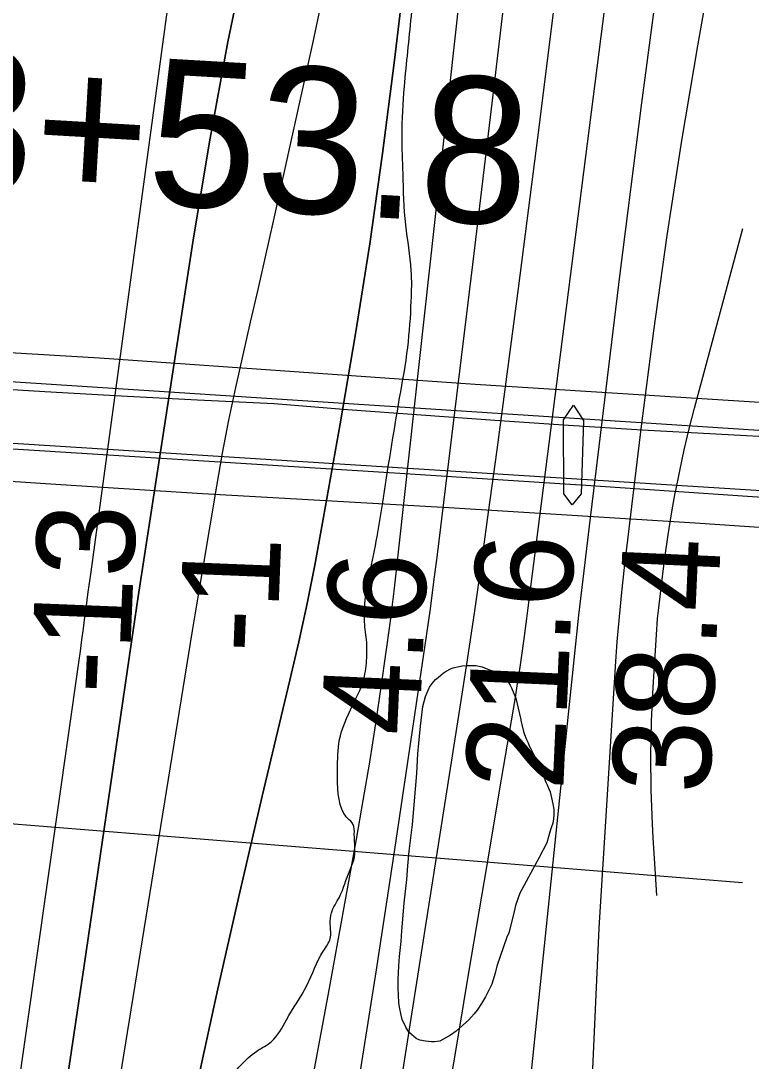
# Model space of a CAD drawing. Extents: x 3297716 to 3335574, y 688621 to 713991.
# Drawn here: x 3325046 to 3325545, y 704839 to 705550 of the extents above; entities that cross this region are included whole.
import ezdxf

# ---------------------------------------------------------------- set-up
doc = ezdxf.new("R2010")
doc.units = 0
for name, color, linetype in [('V-BRDG-OTLN', 7, 'Continuous'), ('V-CHAN-DOCK', 7, 'Continuous'), ('V-RIVR-EDGE', 7, 'Continuous'), ('V-RIVR-RANG', 7, 'Continuous'), ('V-ROAD-CNTR', 7, 'Continuous'), ('V-SITE-VEGE', 7, 'Continuous'), ('V-SURV-IDEN', 7, 'Continuous'), ('V-TOPO-DPTH', 7, 'Continuous'), ('V-TOPO-MAJR', 7, 'Continuous'), ('V-TOPO-MINR', 7, 'Continuous'), ('V-TOPO-WATR', 7, 'Continuous'), ('V-UTIL-LINE', 7, 'Continuous')]:
    doc.layers.add(name, color=color, linetype=linetype)

msp = doc.modelspace()

# ---------------------------------------------------------------- linework, layer by layer
at = {"layer": 'V-BRDG-OTLN'}
for points in [[(3324529.84, 705267.65), (3324534.06, 705355.13), (3324591.79, 705351.33), (3324800.22, 705337.75), (3325099.29, 705319.97), (3325356.02, 705301.98), (3325590.25, 705287.21), (3325902.56, 705266.18)], [(3324573.42, 705329.04), (3324643.35, 705324.88), (3324713.29, 705320.58), (3324783.21, 705316.14), (3324853.14, 705311.57), (3324905.3, 705307.55), (3324957.48, 705303.79), (3325009.68, 705300.29), (3325061.9, 705297.04), (3325114.13, 705294.05), (3325166.38, 705291.31), (3325218.65, 705288.83), (3325268.93, 705284.82), (3325319.23, 705281.02), (3325369.55, 705277.45), (3325419.88, 705274.1), (3325470.22, 705270.97), (3325520.58, 705268.06), (3325570.94, 705265.37), (3325659.01, 705260.29), (3325747.07, 705254.98), (3325835.11, 705249.45), (3325923.14, 705243.69)], [(3324593.65, 705285.89), (3324683.62, 705279.88), (3324773.62, 705274.04), (3324863.63, 705268.39), (3324953.65, 705262.91), (3325043.69, 705257.61), (3325174.19, 705249.55), (3325304.68, 705241.26), (3325435.16, 705232.75), (3325565.62, 705224.02), (3325696.06, 705215.08), (3325790.62, 705209.58), (3325885.17, 705203.87)], [(3325894.43, 705182.98), (3325821.2, 705187.47), (3325747.95, 705191.69), (3325674.68, 705195.66), (3325590.58, 705201.44), (3325506.46, 705207), (3325422.33, 705212.34), (3325338.18, 705217.46), (3325254.01, 705222.35), (3325169.83, 705227.03), (3325072.84, 705233.23), (3324975.84, 705239.55), (3324878.84, 705245.98), (3324781.83, 705252.51), (3324684.83, 705259.16), (3324609.48, 705263.15), (3324534.15, 705267.4), (3324529.84, 705267.65)]]:
    msp.add_lwpolyline(points, dxfattribs=at)
at = {"layer": 'V-CHAN-DOCK'}
msp.add_lwpolyline([(3325416.81, 705227), (3325416.57, 705277.78), (3325423.33, 705287.72), (3325430.2, 705277.22), (3325428.57, 705227.05), (3325422.42, 705219.59)], close=True, dxfattribs=at)
at = {"layer": 'V-RIVR-EDGE'}
msp.add_spline([(3324700.3, 701692.21), (3324707.78, 701736.4), (3324708.99, 701756.57), (3324710.58, 701771.69), (3324714.89, 701788.35), (3324722.34, 701822.07), (3324727.05, 701846.49), (3324726.7, 701860.46), (3324727.5, 701871.7), (3324731.02, 701883.32), (3324734.93, 701894.95), (3324738.07, 701910.07), (3324740.85, 701935.65), (3324742.08, 701963.57), (3324744.08, 701986.84), (3324750.35, 702014.74), (3324758.19, 702047.69), (3324765.99, 702067.83), (3324770.69, 702085.66), (3324776.59, 702119.38), (3324779, 702151.95), (3324775.93, 702165.53), (3324775.95, 702172.13), (3324776.75, 702182.21), (3324782.22, 702198.09), (3324784.57, 702207.4), (3324787.31, 702220.57), (3324790.84, 702234.91), (3324790.48, 702247.32), (3324788.58, 702261.68), (3324792.88, 702276.4), (3324795.23, 702286.48), (3324796.04, 702301.6), (3324796.1, 702322.16), (3324796.58, 702361.71), (3324797.04, 702388.47), (3324797.08, 702405.53), (3324798.28, 702420.65), (3324800.24, 702428.79), (3324800.25, 702434.22), (3324799.12, 702447.41), (3324799.13, 702452.84), (3324801.49, 702463.69), (3324801.9, 702472.61), (3324804.67, 702494.71), (3324803.17, 702516.82), (3324800.1, 702530.78), (3324799.37, 702550.18), (3324800.98, 702572.28), (3324801.8, 702588.95), (3324801.84, 702605.24), (3324799.92, 702613.39), (3324799.56, 702626.19), (3324799.61, 702646.74), (3324796.53, 702655.67), (3324796.55, 702664.2), (3324795.87, 702699.88), (3324799.07, 702741.75), (3324804.98, 702779.74), (3324812.05, 702815.01), (3324811.68, 702822.77), (3324810.22, 702858.07), (3324812.61, 702884.04), (3324819.67, 702918.15), (3324824.8, 702951.1), (3324831.5, 702996.46), (3324832.33, 703018.17), (3324835.5, 703046.86), (3324839.48, 703086.41), (3324850.1, 703144.94), (3324857.56, 703182.54), (3324864.24, 703218.2), (3324872.54, 703282.56), (3324900.83, 703429.08), (3324908.27, 703460.86), (3324916.46, 703480.61), (3324923.86, 703491.84), (3324931.26, 703505.01), (3324939.47, 703529.42), (3324949.64, 703567.01), (3324957.5, 703607.71), (3324964.97, 703649.19), (3324975.98, 703709.27), (3324982.57, 703710.03), (3324987.24, 703714.67), (3324987.29, 703735.23), (3324987.72, 703753.45), (3324992.41, 703770.12), (3324995.53, 703775.92), (3325004.46, 703777.84), (3325009.5, 703779.38), (3325011.06, 703783.64), (3325012.63, 703791.78), (3325016.97, 703820.47), (3325016.6, 703829), (3325013.93, 703846.07), (3325008.93, 703864.31), (3325004.69, 703873.24), (3325006.26, 703880.61), (3325008.99, 703887.58), (3325017.91, 703888.72), (3325028.38, 703888.31), (3325034.21, 703891.78), (3325035, 703896.82), (3325038.14, 703911.16), (3325044.39, 703929.37), (3325050.24, 703944.48), (3325054.93, 703959.21), (3325054.96, 703971.23), (3325056.93, 703984.8), (3325059.31, 704004.96), (3325061.26, 704009.61), (3325066.7, 704013.08), (3325069.03, 704017.34), (3325072.96, 704034.4), (3325083.15, 704079.75), (3325083.58, 704096.81), (3325081.31, 704118.53), (3325074.39, 704143.37), (3325068.22, 704159.67), (3325067.85, 704164.71), (3325072.94, 704185.64), (3325083.49, 704218.97), (3325091.32, 704246.87), (3325097.94, 704259.26), (3325105.32, 704263.9), (3325113.47, 704263.88), (3325125.09, 704261.52), (3325136.71, 704254.12), (3325147.54, 704241.3), (3325156.81, 704227.7), (3325159.92, 704228.86), (3325160.32, 704235.45), (3325158.78, 704241.66), (3325154.93, 704249.43), (3325146.03, 704261.08), (3325125.54, 704282.85), (3325115.1, 704298.78), (3325109.32, 704312.75), (3325105.86, 704323.62), (3325105.49, 704333.31), (3325105.52, 704342.23), (3325105.54, 704350.38), (3325117.67, 704396.5), (3325125.12, 704427.5), (3325138.44, 704482.15), (3325165.86, 704592.22), (3325178.75, 704632.52), (3325185.01, 704655.38), (3325194.42, 704694.53), (3325194.86, 704714.3), (3325191.4, 704727.5), (3325190.64, 704734.48), (3325194.56, 704751.14), (3325194.6, 704767.82), (3325194.64, 704786.05), (3325194.29, 704801.17), (3325187.35, 704813.99), (3325187.75, 704820.97), (3325189.32, 704827.56), (3325195.54, 704836.07), (3325206.82, 704846.13), (3325216.91, 704852.69), (3325227.03, 704867.41), (3325241.05, 704891.03), (3325252.36, 704914.65), (3325257.03, 704923.18), (3325257.06, 704932.87), (3325257.85, 704940.62), (3325263.31, 704951.47), (3325270.33, 704969.68), (3325273.06, 704976.65), (3325273.5, 704994.49), (3325272.74, 705001.08), (3325268.87, 705005.36), (3325263.85, 705014.68), (3325262.32, 705024.38), (3325261.98, 705041.05), (3325263.97, 705061.6), (3325273.72, 705085.24), (3325279.96, 705100.34), (3325281.94, 705115.08), (3325281.96, 705125.55), (3325280.45, 705139.51), (3325280.47, 705148.82), (3325284.02, 705172.08), (3325289.12, 705198.05), (3325292.67, 705219.76), (3325304.48, 705292.63), (3325310, 705327.13), (3325312.4, 705358.93), (3325312.45, 705379.87), (3325308.65, 705410.9), (3325306.8, 705446.2), (3325306.09, 705471.79), (3325307.72, 705505.53), (3325312.5, 705553.61), (3325315.27, 705577.25), (3325322.71, 705605.93), (3325333.67, 705648.56), (3325336.07, 705678.81), (3325335.76, 705709.83), (3325338.11, 705717.97), (3325344.33, 705722.61), (3325351.71, 705730.73), (3325354.45, 705740.81), (3325361.48, 705759.8), (3325365.38, 705767.93), (3325374.72, 705783.42), (3325382.14, 705800.46), (3325392.69, 705833.01), (3325397.79, 705857.43), (3325405.65, 705900.46), (3325409.65, 705948.15), (3325411.66, 705977.23), (3325415.64, 706019.88), (3325415.73, 706054.39), (3325416.61, 706097.05), (3325414.35, 706125.75), (3325407.46, 706162.61), (3325405.59, 706188.21), (3325405.67, 706223.11), (3325404.23, 706268.1), (3325403.6, 706324.72), (3325403.68, 706356.91), (3325406.04, 706372.8), (3325405.68, 706384.82), (3325408.6, 706464.7), (3325405.61, 706509.7), (3325405.31, 706547.7), (3325405.8, 706587.65), (3325414.09, 706646.57), (3325419.6, 706681.85), (3325425.48, 706706.65), (3325425.91, 706723.33), (3325425.55, 706735.74), (3325420.96, 706761.34), (3325415.97, 706779.58), (3325416.8, 706804.01), (3325418.06, 706840.07), (3325420.8, 706852.87), (3325429, 706876.11), (3325434.86, 706890.06), (3325437.2, 706898.59), (3325437.22, 706906.34), (3325430.7, 706932.73), (3325426.49, 706958.33), (3325428.52, 706993.62), (3325433.24, 707021.92), (3325436.36, 707027.73), (3325439.09, 707035.48), (3325443.79, 707052.91), (3325452, 707078.49), (3325452.4, 707085.86), (3325445.46, 707099.45), (3325437.35, 707116.14), (3325435.45, 707129.72), (3325434.74, 707155.71), (3325437.16, 707193.7), (3325443.57, 707277.07), (3325445.56, 707298.78), (3325449.11, 707321.65), (3325456.53, 707344.9), (3325477.62, 707403.02), (3325488.91, 707421.99), (3325492.05, 707435.56), (3325494.41, 707449.9), (3325499.99, 707510.77), (3325504.69, 707528.99), (3325510.97, 707558.44), (3325513.74, 707580.54), (3325514.6, 707615.05), (3325515.06, 707645.69), (3325512.78, 707664.31), (3325511.29, 707691.07), (3325510.62, 707731.4), (3325506.86, 707780.28), (3325505.38, 707807.04), (3325503.84, 707814.41), (3325499.6, 707822.18), (3325498.83, 707826.83), (3325499.62, 707831.87), (3325502.74, 707838.07), (3325504.7, 707846.6), (3325505.89, 707857.06), (3325504.76, 707870.25), (3325502.46, 707882.67), (3325502.1, 707894.69), (3325503.69, 707910.97), (3325508.38, 707924.92), (3325510.73, 707934.23), (3325511.16, 707950.12), (3325515.88, 707978.03), (3325517.14, 708014.49), (3325518.47, 708082.35), (3325523.26, 708136.63), (3325524.9, 708175.79), (3325523.76, 708185.49), (3325521.07, 708195.19), (3325520.7, 708202.17), (3325521.91, 708220.4), (3325524.66, 708236.29), (3325525.88, 708258), (3325524.78, 708283.99), (3325523.65, 708298.34), (3325523.69, 708311.53), (3325525.67, 708328.2), (3325527.24, 708336.72), (3325526.09, 708343.71), (3325524.97, 708360.39), (3325525, 708373.18), (3325527.36, 708384.04), (3325533.23, 708405.35), (3325534.83, 708427.45), (3325536.05, 708449.17), (3325536.49, 708470.11), (3325539.7, 708514.7), (3325540.9, 708527.88), (3325542.48, 708539.51), (3325543.3, 708557.73), (3325546.49, 708594.57), (3325546.96, 708626.36), (3325549.32, 708639.93), (3325548.17, 708644.2), (3325545.85, 708648.47), (3325545.86, 708653.51), (3325548.66, 708688.02), (3325550.73, 708740.37), (3325553.15, 708777.2), (3325553.62, 708810.55), (3325555.63, 708840.8), (3325554.12, 708855.15), (3325554.92, 708867.17), (3325554.95, 708878.03), (3325555.75, 708890.05), (3325555.01, 708903.62), (3325554.27, 708917.97), (3325554.31, 708931.93), (3325555.13, 708949.38), (3325555.55, 708965.67), (3325554.84, 708992.04), (3325554.1, 709005.23), (3325554.13, 709017.64), (3325556.49, 709028.88), (3325556.91, 709042.06), (3325555.04, 709072.71), (3325556.68, 709106.44), (3325555.98, 709137.47), (3325556.83, 709166.16), (3325556.12, 709196.02), (3325555.4, 709218.52), (3325552.35, 709238.3), (3325550.49, 709270.88), (3325549.74, 709282.13), (3325551.33, 709294.54), (3325557.56, 709306.54), (3325563.01, 709315.45), (3325564.98, 709325.53), (3325565, 709334.06), (3325557.32, 709364.72), (3325551.92, 709377.14), (3325545.73, 709382.97), (3325537.6, 709389.97), (3325534.51, 709396.18), (3325531.82, 709405.89), (3325530.68, 709414.42), (3325530.72, 709429.54), (3325531.15, 709448.16), (3325531.58, 709464.83), (3325538.64, 709496.61), (3325542.17, 709510.95), (3325542.19, 709522.2), (3325536.84, 709554.01), (3325527.22, 709584.67), (3325525.7, 709596.7), (3325525.72, 709604.46), (3325526.53, 709618.8), (3325531.21, 709629.65), (3325532.82, 709653.69), (3325533.26, 709673.08), (3325530.62, 709702.95), (3325522.99, 709752.6), (3325519.17, 709778.98), (3325515.75, 709807.3), (3325515.82, 709833.28), (3325518.26, 709880.98), (3325528.52, 709950.37), (3325530.94, 709991.08), (3325532.21, 710034.9), (3325533.92, 710097.72), (3325535.61, 710155.11), (3325530.24, 710177.62), (3325528.34, 710191.58), (3325528.37, 710205.16), (3325527.63, 710217.96), (3325519.13, 710232.33), (3325503.65, 710246.32), (3325495.15, 710257.98), (3325492.87, 710276.21), (3325489.44, 710303.37), (3325485.24, 710326.26), (3325483.8, 710372.41), (3325479.6, 710398.01), (3325474.23, 710425.56), (3325465.39, 710453.89), (3325460.8, 710481.44), (3325458.95, 710517.51), (3325460.99, 710557.06), (3325466.1, 710586.52), (3325467.31, 710604.36), (3325465.82, 710630.73), (3325464.73, 710658.66), (3325467.54, 710697.43), (3325467.24, 710735.05), (3325466.9, 710752.5), (3325466.93, 710764.91), (3325466.2, 710782.75), (3325467.78, 710796.32), (3325469.74, 710804.84), (3325470.15, 710810.66), (3325469.41, 710826.95), (3325464.45, 710858.76), (3325452.53, 710900.67), (3325442.51, 710926.68), (3325430.16, 710951.53), (3325424.01, 710972.88), (3325423.28, 710991.1), (3325424.88, 711012.43), (3325426.86, 711027.16), (3325426.88, 711034.53), (3325424.97, 711046.94), (3325415.73, 711076.05), (3325402.64, 711111.37), (3325394.19, 711146.69), (3325390.03, 711187.03), (3325385.11, 711239.01), (3325374.1, 711332.49), (3325365.36, 711405.81), (3325354.44, 711537.69), (3325349.9, 711583.07), (3325345.01, 711646.3), (3325338.88, 711676.95), (3325338.15, 711695.57), (3325338.18, 711705.65), (3325337.05, 711718.84), (3325330.51, 711741.73), (3325317.82, 711782.48), (3325303.19, 711828.28), (3325297.43, 711850.4), (3325295.54, 711868.63), (3325290.26, 711932.24), (3325286.93, 711996.24), (3325287.08, 712055.19), (3325286.35, 712073.41), (3325282.53, 712096.3), (3325276, 712124.24), (3325270.24, 712146.36), (3325270.26, 712154.5), (3325274.54, 712159.92), (3325277.27, 712165.35), (3325277.67, 712171.16), (3325277.31, 712181.63), (3325276.55, 712187.45), (3325275.01, 712195.21), (3325271.97, 712208.08)], degree=3, dxfattribs=at)
at = {"layer": 'V-ROAD-CNTR'}
for points in [[(3322115.81, 705493.88), (3325973.98, 705243.12), (3326780.38, 705207.88), (3327424.02, 705214.39), (3328124.59, 705236.74), (3328557.68, 705273.44), (3328735.24, 705298.69), (3328852.74, 705321.92), (3328958.57, 705350.2), (3329047.38, 705378.67)], [(3322125.75, 705446.02), (3325883.02, 705208.36), (3326610.25, 705173.62), (3326928.09, 705167.15), (3327579.17, 705181.01), (3328294.95, 705204.66)]]:
    msp.add_lwpolyline(points, dxfattribs=at)
at = {"layer": 'V-SITE-VEGE'}
msp.add_lwpolyline([(3325399.95, 704978.53), (3325386.64, 704954.04), (3325383.7, 704945.66), (3325382.29, 704939.43), (3325379, 704926.95), (3325377.81, 704924.08), (3325370.95, 704904.16), (3325369.77, 704899.37), (3325367.41, 704891.93), (3325364.8, 704886.41), (3325363.14, 704883.29), (3325360.52, 704878.73), (3325357.43, 704874.16), (3325355.52, 704871.52), (3325351.71, 704867.43), (3325343.12, 704859.73), (3325339.3, 704857.08), (3325331.89, 704852.97), (3325328.3, 704852.48), (3325326.15, 704852.47), (3325322.07, 704852.93), (3325318.23, 704853.63), (3325315.83, 704854.82), (3325312.47, 704857.44), (3325310.79, 704859.11), (3325308.61, 704862.45), (3325306.2, 704867.71), (3325305.46, 704870.82), (3325304.48, 704876.09), (3325303.99, 704879.44), (3325303.46, 704889.5), (3325303.44, 704894.77), (3325303.88, 704904.35), (3325304.33, 704910.82), (3325305.48, 704921.12), (3325305.93, 704928.31), (3325307.52, 704947.24), (3325309.37, 704963.54), (3325310.05, 704972.88), (3325310.96, 704982.71), (3325313.28, 705001.16), (3325316.24, 705035.91), (3325316.9, 705049.33), (3325317.59, 705056.76), (3325318.73, 705068.26), (3325320.35, 705081.68), (3325322.24, 705088.63), (3325323.18, 705091.27), (3325324.84, 705094.87), (3325326.75, 705097.52), (3325328.89, 705100.16), (3325331.04, 705101.85), (3325334.14, 705104.5), (3325336.29, 705105.94), (3325339.16, 705107.39), (3325341.07, 705108.12), (3325344.9, 705109.1), (3325347.3, 705109.58), (3325350.89, 705109.84), (3325356.64, 705109.86), (3325360.95, 705108.92), (3325369.35, 705105.37), (3325374.63, 705102.52), (3325377.04, 705100.37), (3325378.48, 705098.7), (3325379.93, 705096.31), (3325380.9, 705094.4), (3325382.59, 705090.57), (3325383.8, 705087.47), (3325386.98, 705073.83), (3325387.47, 705071.19), (3325389.17, 705064.73), (3325389.9, 705062.58), (3325391.11, 705059.23), (3325392.08, 705057.32), (3325393.29, 705054.45), (3325396.67, 705047.76), (3325399.09, 705042.5), (3325400.54, 705038.67), (3325403.21, 705032.94), (3325404.41, 705030.07), (3325405.38, 705028.16), (3325406.35, 705025.53), (3325407.32, 705023.37), (3325409.27, 705015.24), (3325409.76, 705011.41), (3325409.78, 705007.81), (3325409.55, 705004.94), (3325409.09, 705002.06), (3325408.14, 704998.7), (3325407.43, 704996.79), (3325405.08, 704988.63)], close=True, dxfattribs=at)
at = {"layer": 'V-TOPO-DPTH'}
for points in [[(3325165.84, 704822.74), (3325180.18, 704888.78), (3325195.16, 704954.69), (3325210.56, 705020.5), (3325229.51, 705099.78), (3325235.52, 705125.93), (3325241.23, 705152.14), (3325246.47, 705178.45), (3325251.4, 705204.82), (3325263.87, 705274.88), (3325274.29, 705336.41), (3325284.01, 705398.04), (3325292.67, 705459.83), (3325300.64, 705521.73), (3325373.52, 706128.5), (3325374.24, 706134.81), (3325374.9, 706141.12), (3325375.48, 706147.45), (3325376.01, 706153.78), (3325376.47, 706160.11), (3325376.91, 706166.45), (3325377.29, 706172.78), (3325377.65, 706179.12), (3325418.31, 706953.08)], [(3325418.31, 706953.08), (3325377.65, 706179.12), (3325377.29, 706172.78), (3325376.91, 706166.45), (3325376.47, 706160.11), (3325376.01, 706153.78), (3325375.48, 706147.45), (3325374.9, 706141.12), (3325374.24, 706134.81), (3325373.52, 706128.5), (3325300.64, 705521.73), (3325292.67, 705459.83), (3325284.01, 705398.04), (3325274.29, 705336.41), (3325263.87, 705274.88), (3325251.4, 705204.82), (3325246.47, 705178.45), (3325241.23, 705152.14), (3325235.52, 705125.93), (3325229.51, 705099.78), (3325210.56, 705020.5), (3325195.16, 704954.69), (3325180.18, 704888.78), (3325165.84, 704822.74)], [(3325275.74, 704819.63), (3325288.67, 704901.76), (3325301.21, 704983.95), (3325320.19, 705111.36), (3325322.88, 705129.9), (3325325.47, 705148.45), (3325327.92, 705167.02), (3325330.27, 705185.61), (3325354.57, 705383.88), (3325368.73, 705501.64), (3325382.53, 705619.45), (3325395.81, 705737.31), (3325408.74, 705855.21), (3325433.08, 706082), (3325436.25, 706112.59), (3325439.29, 706143.19), (3325442.11, 706173.82), (3325444.8, 706204.46), (3325452.03, 706290.53), (3325458.17, 706364.22), (3325464.24, 706437.91), (3325470.21, 706511.62), (3325476.11, 706585.33), (3325503.74, 706933.62)], [(3325201.11, 705604.08), (3325187.06, 705536.02), (3325174.57, 705467.65), (3325163.14, 705399.08), (3325135.24, 705218.98), (3325130.48, 705187.94), (3325125.78, 705156.9), (3325121.16, 705125.85), (3325116.6, 705094.78), (3325101.19, 704988.71), (3325088.81, 704904.63), (3325076.21, 704820.58)], [(3325201.11, 705604.08), (3325187.06, 705536.02), (3325174.57, 705467.65), (3325163.14, 705399.08), (3325135.24, 705218.98), (3325130.48, 705187.94), (3325125.78, 705156.9), (3325121.16, 705125.85), (3325116.6, 705094.78), (3325101.19, 704988.71), (3325088.81, 704904.63), (3325076.21, 704820.58)]]:
    msp.add_lwpolyline(points, dxfattribs=at)
at = {"layer": 'V-TOPO-MAJR'}
msp.add_lwpolyline([(3325386.47, 704753.23), (3325420.48, 705083.06), (3325423.71, 705113.58), (3325427.05, 705144.09), (3325430.55, 705174.58), (3325434.16, 705205.05), (3325455.1, 705377.72), (3325469.92, 705494.42), (3325485.61, 705611.01), (3325502.62, 705727.41), (3325520.5, 705843.69), (3325563.92, 706115.77), (3325566.28, 706131.54), (3325568.46, 706147.33), (3325570.34, 706163.16), (3325572.03, 706179.02), (3325573.44, 706194.9), (3325574.67, 706210.79), (3325575.65, 706226.71), (3325576.44, 706242.63), (3325605.45, 706936.73)], dxfattribs=at)
at = {"layer": 'V-TOPO-MINR'}
for points in [[(3324963.68, 704259.37), (3325085.17, 705111.81), (3325086.26, 705119.57), (3325087.33, 705127.32), (3325088.38, 705135.08), (3325089.4, 705142.85), (3325090.42, 705150.61), (3325091.45, 705158.37), (3325092.49, 705166.13), (3325093.53, 705173.89), (3325159.71, 705660.6), (3325171.49, 705740.55), (3325184.46, 705820.29), (3325199.19, 705899.72), (3325215.12, 705978.95), (3325353.68, 706984.92)], [(3325275.74, 704819.63), (3325288.67, 704901.76), (3325301.21, 704983.95), (3325320.19, 705111.36), (3325322.88, 705129.9), (3325325.47, 705148.45), (3325327.92, 705167.02), (3325330.27, 705185.61), (3325354.57, 705383.88), (3325368.73, 705501.64), (3325382.53, 705619.45), (3325395.81, 705737.31), (3325408.74, 705855.21), (3325433.08, 706082), (3325436.25, 706112.59), (3325439.29, 706143.19), (3325442.11, 706173.82), (3325444.8, 706204.46), (3325452.03, 706290.53), (3325458.17, 706364.22), (3325464.24, 706437.91), (3325470.21, 706511.62), (3325476.11, 706585.33), (3325503.74, 706933.62)], [(3325241.58, 704808.19), (3325256.1, 704886.65), (3325275.02, 704991.08), (3325279.63, 705017.41), (3325284.04, 705043.76), (3325288.13, 705070.17), (3325292.01, 705096.61), (3325297.9, 705138.45), (3325298.66, 705143.99), (3325299.38, 705149.54), (3325300.06, 705155.1), (3325300.69, 705160.66), (3325366.62, 705757.95), (3325373.49, 705821.9), (3325380.11, 705885.88), (3325386.36, 705949.89), (3325392.36, 706013.92), (3325401.65, 706116.3), (3325402.76, 706129.17), (3325403.8, 706142.04), (3325404.72, 706154.93), (3325405.58, 706167.82), (3325440.8, 706738.58)], [(3325297.08, 704771.32), (3325345.63, 705079.97), (3325350.81, 705113.56), (3325355.83, 705147.17), (3325360.64, 705180.82), (3325365.3, 705214.49), (3325371.08, 705257.25), (3325378.43, 705312.33), (3325385.68, 705367.42), (3325392.76, 705422.53), (3325399.73, 705477.66), (3325459.34, 705954.99)], [(3325271.49, 704422.95), (3325344.83, 704858.43), (3325351.81, 704899.86), (3325358.8, 704941.28), (3325365.8, 704982.71), (3325372.8, 705024.13), (3325383.57, 705087.77), (3325385.14, 705097.38), (3325386.64, 705107), (3325388.03, 705116.64), (3325389.35, 705126.29), (3325391.4, 705141.95), (3325391.63, 705143.78), (3325391.87, 705145.6), (3325392.34, 705149.26), (3325461.84, 705693.43)], [(3325090.71, 704687.03), (3325162.9, 705133.5), (3325164.67, 705144.34), (3325166.45, 705155.19), (3325168.26, 705166.02), (3325170.08, 705176.86), (3325179.47, 705232.39), (3325183.49, 705254.92), (3325187.78, 705277.4), (3325192.47, 705299.79), (3325197.44, 705322.13), (3325202.58, 705344.44), (3325207.67, 705366.76), (3325212.71, 705389.09), (3325217.72, 705411.42), (3325245.21, 705535), (3325262.84, 705619.33)], [(3325436.11, 704823.95), (3325440.75, 704930.28), (3325452.05, 705109.08), (3325453.26, 705126), (3325454.67, 705142.91), (3325456.35, 705159.79), (3325458.23, 705176.65), (3325469.84, 705273.46), (3325478.2, 705338.64), (3325487.27, 705403.71), (3325497.42, 705468.62), (3325508.28, 705533.43), (3325522.18, 705612.39)], [(3325076.21, 704820.58), (3325088.81, 704904.63), (3325101.19, 704988.71), (3325116.6, 705094.78), (3325121.16, 705125.85), (3325125.78, 705156.9), (3325130.48, 705187.94), (3325135.24, 705218.98), (3325163.14, 705399.08), (3325174.57, 705467.65), (3325187.06, 705536.02), (3325201.11, 705604.08)], [(3325480.36, 704952.58), (3325479.53, 704963.65), (3325477.76, 704991.83), (3325477.25, 705001.44), (3325476.4, 705024.85), (3325476.1, 705048.25), (3325476.62, 705071.65), (3325477.68, 705095.04), (3325480.17, 705134.38), (3325480.44, 705138.1), (3325480.75, 705141.82), (3325481.12, 705145.53), (3325481.53, 705149.24), (3325484.08, 705170.54), (3325485.95, 705184.88), (3325488, 705199.18), (3325490.34, 705213.44), (3325492.88, 705227.68), (3325492.99, 705228.26), (3325495.88, 705242.73), (3325499, 705257.15), (3325502.44, 705271.49), (3325506.1, 705285.78), (3325539.04, 705408.58)]]:
    msp.add_lwpolyline(points, dxfattribs=at)
at = {"layer": 'V-TOPO-WATR'}
msp.add_lwpolyline([(3325165.84, 704822.74), (3325180.18, 704888.78), (3325195.16, 704954.69), (3325210.56, 705020.5), (3325229.51, 705099.78), (3325235.52, 705125.93), (3325241.23, 705152.14), (3325246.47, 705178.45), (3325251.4, 705204.82), (3325263.87, 705274.88), (3325274.29, 705336.41), (3325284.01, 705398.04), (3325292.67, 705459.83), (3325300.64, 705521.73), (3325373.52, 706128.5), (3325374.24, 706134.81), (3325374.9, 706141.12), (3325375.48, 706147.45), (3325376.01, 706153.78), (3325376.47, 706160.11), (3325376.91, 706166.45), (3325377.29, 706172.78), (3325377.65, 706179.12), (3325418.31, 706953.08)], dxfattribs=at)
at = {"layer": 'V-UTIL-LINE'}
msp.add_line((3325538.84, 704961.18), (3322250.65, 705225.51), dxfattribs=at)

# ---------------------------------------------------------------- texts
at = {"layer": 'V-RIVR-RANG'}
for s, rotation, p in [('-13', 87.7065, (3325119.22, 705089.43)), ('-1', 87.7065, (3325220.43, 705117.6)), ('21.6', 87.41833, (3325416.23, 705023.82)), ('38.4', 87.41833, (3325516.22, 705021.42)), ('4.6', 87.41833, (3325317.81, 705061.28))]:
    msp.add_text(s, height=67, rotation=rotation, dxfattribs=at).set_placement(p)
at = {"layer": 'V-SURV-IDEN'}
msp.add_text('83+53.8', height=100, rotation=356.65806, dxfattribs=at).set_placement((3324904.04, 705438.59))

doc.saveas('drawing.dxf')
